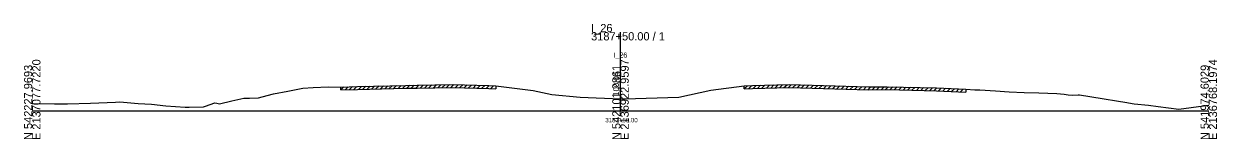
# Model space of a CAD drawing. Extents: x -13101 to 4803, y -924 to 22390.
# Drawn here: x 997.2 to 1402.8, y 13490.3 to 13529.5 of the extents above; entities that cross this region are included whole.
import ezdxf

# ---------------------------------------------------------------- set-up
doc = ezdxf.new("R2010")
doc.units = 0
for name, color, linetype in [('RD_GPK_XS_Cell', 7, 'Continuous'), ('RD_XS_ExGround', 7, 'Continuous'), ('RD_XS_ExPaveRet', 7, 'Continuous'), ('RD_XS_TX_Baseline', 7, 'Continuous'), ('RD_XS_TX_Elev_EX', 7, 'Continuous'), ('RD_XS_TX_Station', 7, 'Continuous')]:
    doc.layers.add(name, color=color, linetype=linetype)

msp = doc.modelspace()

# ---------------------------------------------------------------- linework, layer by layer
at = {"layer": 'RD_GPK_XS_Cell'}
for p, q in [((1200, 13500), (1200, 13526.71)), ((1000, 13500), (1200, 13500)), ((1200, 13500), (1400, 13500))]:
    msp.add_line(p, q, dxfattribs=at)
at = {"layer": 'RD_XS_ExGround'}
msp.add_lwpolyline([(1000, 13502.4), (1007.54, 13502.31), (1012, 13502.34), (1019.79, 13502.51), (1028.36, 13502.91), (1029.79, 13502.97), (1035.97, 13502.41), (1040.54, 13502.21), (1045.45, 13501.61), (1051.96, 13501.16), (1053.3, 13501.21), (1058.2, 13501.36), (1061.18, 13502.36), (1061.96, 13502.67), (1062.71, 13502.51), (1063.65, 13502.35), (1067.9, 13503.3), (1071.97, 13504.23), (1073.86, 13504.26), (1076.97, 13504.32), (1079.93, 13505.11), (1081.98, 13505.68), (1086.89, 13506.67), (1091.99, 13507.63), (1095.51, 13507.85), (1100.66, 13508.09), (1104.87, 13508.05), (1110.6, 13508.26), (1127.05, 13508.61), (1130.86, 13508.66), (1142.92, 13508.9), (1155.27, 13508.54), (1157.64, 13508.46), (1170.27, 13506.91), (1176.69, 13505.48), (1186.34, 13504.6), (1200, 13504.04), (1201.36, 13503.99), (1219.83, 13504.55), (1230.76, 13507.02), (1242.08, 13508.45), (1244.9, 13508.56), (1257.34, 13508.87), (1269.07, 13508.57), (1284.34, 13508.08), (1290.69, 13508.15), (1307.47, 13507.75), (1317.38, 13507.3), (1320.45, 13507.12), (1322.18, 13507.04), (1327.48, 13506.73), (1332.18, 13506.46), (1337.23, 13506.21), (1342.19, 13506.04), (1345.26, 13505.91), (1348.3, 13505.84), (1350.78, 13505.58), (1352.2, 13505.38), (1353.58, 13505.3), (1355.58, 13505.34), (1356.1, 13505.36), (1363.78, 13504.1), (1369.25, 13503.29), (1371.47, 13502.94), (1374.6, 13502.38), (1379.5, 13501.83), (1382.8, 13501.45), (1389.87, 13500.52), (1398.16, 13501.64), (1400, 13501.89)], dxfattribs=at)
at = {"layer": 'RD_XS_ExPaveRet'}
for p, q in [((1104.87, 13507.05), (1105.91, 13508.08)), ((1104.87, 13507.05), (1104.87, 13508.05)), ((1104.87, 13507.05), (1110.6, 13507.26)), ((1106.37, 13507.1), (1107.41, 13508.14)), ((1107.87, 13507.16), (1108.91, 13508.19)), ((1109.37, 13507.21), (1110.41, 13508.25)), ((1110.6, 13507.26), (1127.05, 13507.61)), ((1110.87, 13507.26), (1111.9, 13508.28)), ((1112.37, 13507.29), (1113.4, 13508.32)), ((1113.87, 13507.33), (1114.9, 13508.35)), ((1115.37, 13507.36), (1116.4, 13508.38)), ((1116.87, 13507.39), (1117.9, 13508.41)), ((1118.37, 13507.42), (1119.4, 13508.45)), ((1119.87, 13507.46), (1120.9, 13508.48)), ((1121.37, 13507.49), (1122.4, 13508.51)), ((1122.87, 13507.52), (1123.9, 13508.54)), ((1124.37, 13507.55), (1125.4, 13508.58)), ((1125.87, 13507.59), (1126.9, 13508.61)), ((1127.05, 13507.61), (1130.86, 13507.66)), ((1127.37, 13507.62), (1128.39, 13508.63)), ((1128.87, 13507.64), (1129.89, 13508.65)), ((1130.37, 13507.66), (1131.39, 13508.67)), ((1130.86, 13507.66), (1142.92, 13507.9)), ((1131.87, 13507.68), (1132.89, 13508.7)), ((1133.37, 13507.71), (1134.39, 13508.73)), ((1134.87, 13507.74), (1135.89, 13508.76)), ((1136.37, 13507.77), (1137.39, 13508.79)), ((1137.87, 13507.8), (1138.89, 13508.82)), ((1139.37, 13507.83), (1140.39, 13508.85)), ((1140.87, 13507.86), (1141.89, 13508.88)), ((1142.37, 13507.89), (1143.37, 13508.89)), ((1142.92, 13507.9), (1155.27, 13507.54)), ((1143.87, 13507.87), (1144.84, 13508.85)), ((1145.37, 13507.83), (1146.34, 13508.8)), ((1146.87, 13507.79), (1147.84, 13508.76)), ((1148.37, 13507.74), (1149.34, 13508.71)), ((1149.87, 13507.7), (1150.84, 13508.67)), ((1151.37, 13507.65), (1152.34, 13508.62)), ((1152.87, 13507.61), (1153.84, 13508.58)), ((1154.37, 13507.56), (1155.34, 13508.54)), ((1155.27, 13507.54), (1157.64, 13507.46)), ((1155.87, 13507.52), (1156.84, 13508.48)), ((1157.64, 13508.46), (1157.64, 13507.46)), ((1242.08, 13507.45), (1243.12, 13508.49)), ((1242.08, 13507.45), (1242.08, 13508.45)), ((1242.08, 13507.45), (1244.9, 13507.56)), ((1243.58, 13507.51), (1244.62, 13508.55)), ((1244.9, 13507.56), (1257.34, 13507.87)), ((1245.08, 13507.56), (1246.11, 13508.59)), ((1246.58, 13507.6), (1247.61, 13508.63)), ((1248.08, 13507.64), (1249.11, 13508.66)), ((1249.58, 13507.68), (1250.61, 13508.7)), ((1251.08, 13507.71), (1252.11, 13508.74)), ((1252.58, 13507.75), (1253.61, 13508.78)), ((1254.08, 13507.79), (1255.11, 13508.81)), ((1255.58, 13507.83), (1256.61, 13508.85)), ((1257.08, 13507.86), (1258.07, 13508.85)), ((1257.34, 13507.87), (1269.07, 13507.57)), ((1258.58, 13507.84), (1259.56, 13508.81)), ((1260.08, 13507.8), (1261.06, 13508.78)), ((1261.58, 13507.76), (1262.56, 13508.74)), ((1263.08, 13507.72), (1264.06, 13508.7)), ((1264.58, 13507.69), (1265.56, 13508.66)), ((1266.08, 13507.65), (1267.06, 13508.62)), ((1267.58, 13507.61), (1268.56, 13508.58)), ((1269.07, 13507.57), (1284.34, 13507.08)), ((1269.08, 13507.57), (1270.05, 13508.54)), ((1270.58, 13507.52), (1271.55, 13508.49)), ((1272.08, 13507.47), (1273.05, 13508.44)), ((1273.58, 13507.43), (1274.55, 13508.4)), ((1275.08, 13507.38), (1276.05, 13508.35)), ((1276.58, 13507.33), (1277.55, 13508.3)), ((1278.08, 13507.28), (1279.05, 13508.25)), ((1279.58, 13507.24), (1280.55, 13508.2)), ((1281.08, 13507.19), (1282.05, 13508.16)), ((1282.58, 13507.14), (1283.55, 13508.11)), ((1284.08, 13507.09), (1285.08, 13508.09)), ((1284.34, 13507.08), (1290.69, 13507.15)), ((1285.58, 13507.1), (1286.59, 13508.11)), ((1287.08, 13507.11), (1288.09, 13508.12)), ((1288.58, 13507.13), (1289.59, 13508.14)), ((1290.08, 13507.15), (1291.08, 13508.14)), ((1290.69, 13507.15), (1307.47, 13506.75)), ((1291.58, 13507.13), (1292.56, 13508.11)), ((1293.08, 13507.09), (1294.06, 13508.07)), ((1294.58, 13507.06), (1295.56, 13508.03)), ((1296.08, 13507.02), (1297.06, 13508)), ((1297.58, 13506.99), (1298.56, 13507.96)), ((1299.08, 13506.95), (1300.06, 13507.93)), ((1300.58, 13506.91), (1301.56, 13507.89)), ((1302.08, 13506.88), (1303.06, 13507.85)), ((1303.58, 13506.84), (1304.56, 13507.82)), ((1305.08, 13506.8), (1306.06, 13507.78)), ((1306.58, 13506.77), (1307.56, 13507.74)), ((1307.47, 13506.75), (1317.38, 13506.3)), ((1308.08, 13506.72), (1309.04, 13507.68)), ((1309.58, 13506.65), (1310.54, 13507.61)), ((1311.08, 13506.58), (1312.04, 13507.54)), ((1312.58, 13506.52), (1313.54, 13507.47)), ((1314.08, 13506.45), (1315.04, 13507.41)), ((1315.58, 13506.38), (1316.54, 13507.34)), ((1317.38, 13507.3), (1317.38, 13506.3))]:
    msp.add_line(p, q, dxfattribs=at)

# ---------------------------------------------------------------- texts
at = {"layer": 'RD_GPK_XS_Cell'}
for s, p in [('I_26', (1190, 13526.71)), ('3187+50.00 / 1', (1190, 13523.91))]:
    msp.add_text(s, height=2.8, dxfattribs=at).set_placement(p)
for s, p in [('E 2137077.7220', (1002.8, 13490)), ('E 2136768.1974', (1402.8, 13490)), ('N 542227.9693', (1000, 13490)), ('N 542101.2861', (1200, 13490)), ('E 2136922.9597', (1202.8, 13490)), ('N 541974.6029', (1400, 13490))]:
    msp.add_text(s, height=2.8, rotation=90, dxfattribs=at).set_placement(p)
at = {"layer": 'RD_XS_TX_Baseline'}
msp.add_text('I_26', height=1.75, dxfattribs=at).set_placement((1197.6, 13518.04))
at = {"layer": 'RD_XS_TX_Elev_EX'}
msp.add_text('100.04', height=2, rotation=90, dxfattribs=at).set_placement((1199.5, 13505.04))
at = {"layer": 'RD_XS_TX_Station'}
msp.add_text('3187+50.00', height=1.5, dxfattribs=at).set_placement((1194.84, 13496.04))

doc.saveas('drawing.dxf')
